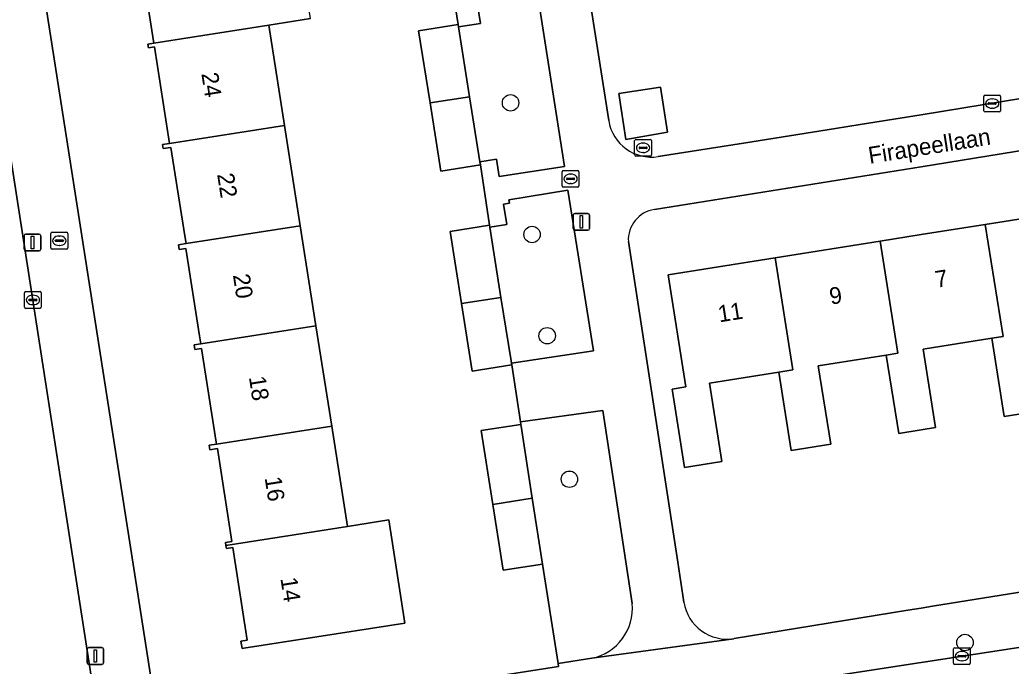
# Model space of a CAD drawing. Extents: x 160077 to 160948, y 386481 to 387498.
# Drawn here: x 160446.3 to 160505.4, y 387335.6 to 387374.1 of the extents above; entities that cross this region are included whole.
import ezdxf

# ---------------------------------------------------------------- set-up
doc = ezdxf.new("R2010")
doc.units = 0
for name, color, linetype in [('IMGEO_Boom', 7, 'Continuous'), ('IMGEO_Brandkraan', 7, 'Continuous'), ('IMGEO_Erf', 7, 'Continuous'), ('IMGEO_Groenvoorziening', 7, 'Continuous'), ('IMGEO_Kolk', 7, 'Continuous'), ('IMGEO_Lichtmast', 7, 'Continuous'), ('IMGEO_Openbare_ruimte_label', 7, 'Continuous'), ('IMGEO_Pand', 7, 'Continuous'), ('IMGEO_Pand_nummerreeks', 7, 'Continuous'), ('IMGEO_Rijbaan_lokaal_open', 7, 'Continuous'), ('IMGEO_Rioolput', 7, 'Continuous'), ('IMGEO_Voetpad_open', 7, 'Continuous')]:
    doc.layers.add(name, color=color, linetype=linetype)

msp = doc.modelspace()

# ---------------------------------------------------------------- linework, layer by layer
at = {"layer": 'IMGEO_Boom'}
for centre in [(160475.515, 387369.198), (160476.8, 387361.347), (160477.699, 387355.309), (160479.027, 387346.755), (160502.615, 387337.017)]:
    msp.add_circle(centre, 0.489, dxfattribs=at)
at = {"layer": 'IMGEO_Brandkraan'}
for p, q in [((160448.107, 387360.55), (160448.107, 387361.402)), ((160448.182, 387361.476), (160449.034, 387361.476)), ((160448.595, 387361.256), (160448.62, 387361.256)), ((160449.108, 387361.402), (160449.108, 387360.55)), ((160448.366, 387360.97), (160448.366, 387360.982)), ((160448.804, 387360.933), (160448.406, 387360.933)), ((160448.409, 387361.019), (160448.807, 387361.019)), ((160448.618, 387360.696), (160448.593, 387360.696)), ((160448.85, 387360.982), (160448.85, 387360.97)), ((160449.034, 387360.476), (160448.182, 387360.476))]:
    msp.add_line(p, q, dxfattribs=at)
for points in [[(160448.107, 387360.55), (160448.107, 387361.402)], [(160448.182, 387361.476), (160449.034, 387361.476)], [(160449.108, 387361.402), (160449.108, 387360.55)], [(160449.034, 387360.476), (160448.182, 387360.476)]]:
    msp.add_lwpolyline(points, dxfattribs=at)
for centre, radius, start, end in [((160448.184, 387361.4), 0.0765, 91.55205, 178.44795), ((160448.184, 387361.4), 0.0765, 91.55205, 178.44795), ((160449.032, 387361.4), 0.0765, 1.55205, 88.44795), ((160449.032, 387361.4), 0.0765, 1.55205, 88.44795), ((160448.406, 387360.979), 0.0403, 85.87752, 175.75265), ((160448.403, 387360.969), 0.0366, 178.93798, 274.71019), ((160448.807, 387360.976), 0.043, 264.86636, 352.45326), ((160448.811, 387360.981), 0.0386, 1.73085, 96.63898), ((160448.184, 387360.552), 0.0765, 181.55205, 268.44795), ((160448.184, 387360.552), 0.0765, 181.55205, 268.44795), ((160449.032, 387360.552), 0.0765, 271.55205, 358.44795), ((160449.032, 387360.552), 0.0765, 271.55205, 358.44795)]:
    msp.add_arc(centre, radius, start, end, dxfattribs=at)
for centre, major_axis, ratio, start_param, end_param in [((160448.594, 387360.976), (-0.387, 0.002), 0.722429, 4.712389, 7.853982), ((160448.619, 387360.976), (-0.39, 0.002), 0.717154, 1.570796, 4.712389)]:
    msp.add_ellipse(centre, major_axis=major_axis, ratio=ratio, start_param=start_param, end_param=end_param, dxfattribs=at)
at = {"layer": 'IMGEO_Erf'}
for points in [[(160468.816, 387381.159), (160468.202, 387385.029), (160470.554, 387385.403), (160469.911, 387389.457), (160467.557, 387389.085), (160466.918, 387393.126), (160466.238, 387397.42), (160468.592, 387397.792), (160468.029, 387401.353), (160465.675, 387400.981), (160465.025, 387405.092), (160464.34, 387409.42), (160466.693, 387409.792), (160466.137, 387413.304), (160463.783, 387412.932), (160463.13, 387417.058), (160462.455, 387421.323), (160464.809, 387421.695), (160464.247, 387425.247), (160440.528, 387421.423), (160454.195, 387334.054)], [(160478.041, 387389.373), (160481.371, 387368.134)], [(160456.866, 387332.235), (160478.373, 387335.585), (160478.346, 387335.761), (160477.421, 387341.696), (160475.067, 387341.33), (160474.455, 387345.254), (160473.769, 387349.66), (160476.123, 387350.026), (160476.101, 387350.173), (160475.583, 387353.575), (160473.23, 387353.201), (160472.591, 387357.225), (160471.91, 387361.519), (160474.263, 387361.893), (160473.715, 387365.492), (160471.363, 387365.118), (160470.715, 387369.195), (160470.033, 387373.491), (160472.386, 387373.865), (160471.813, 387377.477), (160469.46, 387377.103), (160468.816, 387381.159)], [(160463.577, 387374.218), (160461.106, 387373.831), (160462.041, 387367.854), (160462.977, 387361.866), (160463.913, 387355.9), (160464.849, 387349.922), (160465.785, 387343.945), (160468.252, 387344.331), (160469.214, 387338.181), (160468.307, 387338.039), (160459.618, 387336.678), (160459.507, 387336.661), (160459.438, 387337.103), (160459.814, 387337.162), (160458.949, 387342.685), (160458.568, 387342.625), (160458.539, 387342.811), (160458.514, 387342.973), (160458.9, 387343.034), (160458.031, 387348.585), (160457.576, 387348.514), (160457.535, 387348.777), (160457.97, 387348.845), (160457.952, 387348.959), (160457.077, 387354.547), (160456.692, 387354.487), (160456.648, 387354.763), (160457.049, 387354.826), (160456.973, 387355.311), (160456.158, 387360.515), (160455.753, 387360.452), (160455.708, 387360.739), (160456.163, 387360.81), (160456.091, 387361.271), (160455.265, 387366.54), (160454.802, 387366.468), (160454.765, 387366.704), (160455.186, 387366.77), (160454.284, 387372.531), (160453.919, 387372.474), (160453.883, 387372.7), (160454.236, 387372.763), (160453.345, 387378.454)], [(160484.327, 387365.994), (160489.406, 387366.799), (160494.896, 387367.669), (160496.357, 387367.901), (160500, 387368.49), (160507.39, 387369.685), (160508.893, 387369.93), (160514.628, 387370.867), (160520.489, 387371.785), (160521.678, 387371.943)], [(160522.075, 387368.967), (160520.672, 387368.738), (160500, 387365.375), (160484.096, 387362.839)], [(160507.096, 387350.827), (160504.961, 387350.487), (160504.219, 387355.157), (160500.12, 387354.505), (160500.862, 387349.835), (160500, 387349.698), (160498.667, 387349.486), (160497.925, 387354.156), (160493.867, 387353.511), (160494.61, 387348.841), (160492.256, 387348.467), (160491.513, 387353.136), (160487.377, 387352.478), (160488.12, 387347.808), (160485.895, 387347.454), (160485.152, 387352.124), (160485.974, 387352.255), (160484.911, 387358.939), (160491.287, 387359.953), (160497.557, 387360.95), (160500, 387361.339), (160503.828, 387361.948), (160510.098, 387362.945)], [(160482.54, 387360.92), (160485.484, 387341.815), (160485.854, 387339.415)], [(160488.852, 387337.254), (160499.213, 387338.948), (160500, 387339.075), (160500.683, 387339.185), (160505.767, 387339.991), (160519.324, 387342.142), (160523.935, 387342.867), (160526.171, 387343.197)]]:
    msp.add_lwpolyline(points, dxfattribs=at)
msp.add_lwpolyline([(160482.392, 387367.019), (160481.976, 387369.76), (160484.464, 387370.138), (160484.873, 387367.448)], close=True, dxfattribs=at)
for centre, radius, start, end in [((160483.922, 387368.547), 2.585, 189.18775, 279.00684), ((160484.374, 387361.023), 1.837, 98.70088, 183.22614), ((160488.429, 387339.828), 2.608, 189.10238, 279.32845)]:
    msp.add_arc(centre, radius, start, end, dxfattribs=at)
at = {"layer": 'IMGEO_Groenvoorziening'}
for points in [[(160477.106, 387375.835), (160473.51, 387375.257), (160473.524, 387375.163), (160473.719, 387373.933), (160472.408, 387373.725), (160473.069, 387369.563), (160473.685, 387365.68), (160474.673, 387365.836), (160474.837, 387364.8), (160478.735, 387365.403)], [(160478.936, 387363.988), (160475.413, 387363.407), (160475.443, 387363.21), (160475.097, 387363.155), (160475.289, 387361.944), (160474.28, 387361.784), (160474.945, 387357.594), (160475.544, 387353.822), (160475.569, 387353.666), (160480.463, 387354.419)]]:
    msp.add_lwpolyline(points, close=True, dxfattribs=at)
for points in [[(160481.012, 387350.858), (160476.101, 387350.173), (160476.123, 387350.026), (160476.141, 387349.913), (160476.809, 387345.623), (160477.421, 387341.696), (160478.346, 387335.761), (160480.358, 387336.079)], [(160482.768, 387339.346), (160481.012, 387350.858)]]:
    msp.add_lwpolyline(points, dxfattribs=at)
msp.add_arc((160479.739, 387339.058), 3.042, 281.73362, 5.43548, dxfattribs=at)
at = {"layer": 'IMGEO_Kolk'}
for p, q in [((160503.737, 387368.729), (160503.737, 387369.581)), ((160503.812, 387369.655), (160504.664, 387369.655)), ((160504.738, 387369.581), (160504.738, 387368.729)), ((160503.996, 387369.149), (160503.996, 387369.161)), ((160504.434, 387369.112), (160504.036, 387369.112)), ((160504.039, 387369.198), (160504.437, 387369.198)), ((160504.225, 387369.435), (160504.25, 387369.435)), ((160504.48, 387369.161), (160504.48, 387369.149)), ((160504.664, 387368.655), (160503.812, 387368.655)), ((160504.248, 387368.875), (160504.223, 387368.875)), ((160478.594, 387364.24), (160478.594, 387365.092)), ((160478.669, 387365.166), (160479.521, 387365.166)), ((160479.082, 387364.946), (160479.107, 387364.946)), ((160479.595, 387365.092), (160479.595, 387364.24)), ((160479.521, 387364.166), (160478.669, 387364.166)), ((160478.853, 387364.66), (160478.853, 387364.672)), ((160479.291, 387364.623), (160478.893, 387364.623)), ((160478.896, 387364.709), (160479.294, 387364.709)), ((160479.105, 387364.386), (160479.08, 387364.386)), ((160479.337, 387364.672), (160479.337, 387364.66)), ((160446.53, 387357.017), (160446.53, 387357.869)), ((160446.605, 387357.943), (160447.457, 387357.943)), ((160447.018, 387357.723), (160447.043, 387357.723)), ((160447.531, 387357.869), (160447.531, 387357.017)), ((160446.789, 387357.437), (160446.789, 387357.449)), ((160447.227, 387357.4), (160446.829, 387357.4)), ((160446.832, 387357.486), (160447.23, 387357.486)), ((160447.041, 387357.163), (160447.016, 387357.163)), ((160447.273, 387357.449), (160447.273, 387357.437)), ((160447.457, 387356.943), (160446.605, 387356.943)), ((160501.931, 387335.781), (160501.931, 387336.633)), ((160502.006, 387336.707), (160502.858, 387336.707)), ((160502.419, 387336.487), (160502.444, 387336.487)), ((160502.932, 387336.633), (160502.932, 387335.781)), ((160502.19, 387336.201), (160502.19, 387336.213)), ((160502.628, 387336.164), (160502.23, 387336.164)), ((160502.233, 387336.25), (160502.631, 387336.25)), ((160502.442, 387335.927), (160502.417, 387335.927)), ((160502.674, 387336.213), (160502.674, 387336.201)), ((160502.858, 387335.707), (160502.006, 387335.707))]:
    msp.add_line(p, q, dxfattribs=at)
for points in [[(160503.737, 387368.729), (160503.737, 387369.581)], [(160503.812, 387369.655), (160504.664, 387369.655)], [(160504.738, 387369.581), (160504.738, 387368.729)], [(160504.664, 387368.655), (160503.812, 387368.655)], [(160478.594, 387364.24), (160478.594, 387365.092)], [(160478.669, 387365.166), (160479.521, 387365.166)], [(160479.595, 387365.092), (160479.595, 387364.24)], [(160479.521, 387364.166), (160478.669, 387364.166)], [(160446.53, 387357.017), (160446.53, 387357.869)], [(160446.605, 387357.943), (160447.457, 387357.943)], [(160447.531, 387357.869), (160447.531, 387357.017)], [(160447.457, 387356.943), (160446.605, 387356.943)], [(160501.931, 387335.781), (160501.931, 387336.633)], [(160502.006, 387336.707), (160502.858, 387336.707)], [(160502.932, 387336.633), (160502.932, 387335.781)], [(160502.858, 387335.707), (160502.006, 387335.707)]]:
    msp.add_lwpolyline(points, dxfattribs=at)
for centre, radius, start, end in [((160503.814, 387369.579), 0.0765, 91.55205, 178.44795), ((160503.814, 387369.579), 0.0765, 91.55205, 178.44795), ((160504.662, 387369.579), 0.0765, 1.55205, 88.44795), ((160504.662, 387369.579), 0.0765, 1.55205, 88.44795), ((160504.036, 387369.158), 0.0403, 85.87752, 175.75265), ((160504.033, 387369.148), 0.0366, 178.93798, 274.71019), ((160504.437, 387369.155), 0.043, 264.86636, 352.45326), ((160504.441, 387369.16), 0.0386, 1.73085, 96.63898), ((160503.814, 387368.731), 0.0765, 181.55205, 268.44795), ((160503.814, 387368.731), 0.0765, 181.55205, 268.44795), ((160504.662, 387368.731), 0.0765, 271.55205, 358.44795), ((160504.662, 387368.731), 0.0765, 271.55205, 358.44795), ((160478.671, 387365.09), 0.0765, 91.55205, 178.44795), ((160478.671, 387365.09), 0.0765, 91.55205, 178.44795), ((160479.519, 387365.09), 0.0765, 1.55205, 88.44795), ((160479.519, 387365.09), 0.0765, 1.55205, 88.44795), ((160478.671, 387364.242), 0.0765, 181.55205, 268.44795), ((160478.671, 387364.242), 0.0765, 181.55205, 268.44795), ((160478.893, 387364.669), 0.0403, 85.87752, 175.75265), ((160478.89, 387364.659), 0.0366, 178.93798, 274.71019), ((160479.294, 387364.666), 0.043, 264.86636, 352.45326), ((160479.298, 387364.671), 0.0386, 1.73085, 96.63898), ((160479.519, 387364.242), 0.0765, 271.55205, 358.44795), ((160479.519, 387364.242), 0.0765, 271.55205, 358.44795), ((160446.607, 387357.867), 0.0765, 91.55205, 178.44795), ((160446.607, 387357.867), 0.0765, 91.55205, 178.44795), ((160447.455, 387357.867), 0.0765, 1.55205, 88.44795), ((160447.455, 387357.867), 0.0765, 1.55205, 88.44795), ((160446.829, 387357.446), 0.0403, 85.87752, 175.75265), ((160446.826, 387357.436), 0.0366, 178.93798, 274.71019), ((160447.23, 387357.443), 0.043, 264.86636, 352.45326), ((160447.234, 387357.448), 0.0386, 1.73085, 96.63898), ((160446.607, 387357.019), 0.0765, 181.55205, 268.44795), ((160446.607, 387357.019), 0.0765, 181.55205, 268.44795), ((160447.455, 387357.019), 0.0765, 271.55205, 358.44795), ((160447.455, 387357.019), 0.0765, 271.55205, 358.44795), ((160502.008, 387336.631), 0.0765, 91.55205, 178.44795), ((160502.008, 387336.631), 0.0765, 91.55205, 178.44795), ((160502.856, 387336.631), 0.0765, 1.55205, 88.44795), ((160502.856, 387336.631), 0.0765, 1.55205, 88.44795), ((160502.008, 387335.783), 0.0765, 181.55205, 268.44795), ((160502.008, 387335.783), 0.0765, 181.55205, 268.44795), ((160502.23, 387336.21), 0.0403, 85.87752, 175.75265), ((160502.227, 387336.2), 0.0366, 178.93798, 274.71019), ((160502.631, 387336.207), 0.043, 264.86636, 352.45326), ((160502.635, 387336.212), 0.0386, 1.73085, 96.63898), ((160502.856, 387335.783), 0.0765, 271.55205, 358.44795), ((160502.856, 387335.783), 0.0765, 271.55205, 358.44795)]:
    msp.add_arc(centre, radius, start, end, dxfattribs=at)
for centre, major_axis, ratio, start_param, end_param in [((160504.224, 387369.155), (-0.387, 0.002), 0.722429, 4.712389, 7.853982), ((160504.249, 387369.155), (-0.39, 0.002), 0.717154, 1.570796, 4.712389), ((160479.081, 387364.666), (-0.387, 0.002), 0.722429, 4.712389, 7.853982), ((160479.106, 387364.666), (-0.39, 0.002), 0.717154, 1.570796, 4.712389), ((160447.017, 387357.443), (-0.387, 0.002), 0.722429, 4.712389, 7.853982), ((160447.042, 387357.443), (-0.39, 0.002), 0.717154, 1.570796, 4.712389), ((160502.418, 387336.207), (-0.387, 0.002), 0.722429, 4.712389, 7.853982), ((160502.443, 387336.207), (-0.39, 0.002), 0.717154, 1.570796, 4.712389)]:
    msp.add_ellipse(centre, major_axis=major_axis, ratio=ratio, start_param=start_param, end_param=end_param, dxfattribs=at)
at = {"layer": 'IMGEO_Lichtmast'}
for p, q in [((160479.243, 387361.697), (160479.243, 387362.497)), ((160479.243, 387362.497), (160479.243, 387361.697)), ((160479.343, 387362.597), (160480.133, 387362.597)), ((160480.133, 387362.597), (160479.343, 387362.597)), ((160480.233, 387362.497), (160480.233, 387361.697)), ((160480.233, 387361.697), (160480.233, 387362.497)), ((160446.507, 387360.468), (160446.507, 387361.268)), ((160446.507, 387361.268), (160446.507, 387360.468)), ((160446.607, 387361.368), (160447.397, 387361.368)), ((160447.397, 387361.368), (160446.607, 387361.368)), ((160447.497, 387361.268), (160447.497, 387360.468)), ((160447.497, 387360.468), (160447.497, 387361.268)), ((160480.133, 387361.597), (160479.343, 387361.597)), ((160479.343, 387361.597), (160480.133, 387361.597)), ((160447.397, 387360.368), (160446.607, 387360.368)), ((160446.607, 387360.368), (160447.397, 387360.368)), ((160450.259, 387335.815), (160450.259, 387336.615)), ((160450.259, 387336.615), (160450.259, 387335.815)), ((160450.359, 387336.715), (160451.149, 387336.715)), ((160451.149, 387336.715), (160450.359, 387336.715)), ((160451.249, 387336.615), (160451.249, 387335.815)), ((160451.249, 387335.815), (160451.249, 387336.615)), ((160451.149, 387335.715), (160450.359, 387335.715)), ((160450.359, 387335.715), (160451.149, 387335.715))]:
    msp.add_line(p, q, dxfattribs=at)
for points in [[(160479.663, 387362.472), (160479.813, 387362.472), (160479.813, 387361.722), (160479.663, 387361.722), (160479.663, 387362.472)], [(160446.927, 387361.243), (160447.077, 387361.243), (160447.077, 387360.493), (160446.927, 387360.493), (160446.927, 387361.243)], [(160450.679, 387336.59), (160450.829, 387336.59), (160450.829, 387335.84), (160450.679, 387335.84), (160450.679, 387336.59)]]:
    msp.add_lwpolyline(points, dxfattribs=at)
for centre, start, end in [((160479.343, 387362.497), 90, 180), ((160479.343, 387362.497), 90, 180), ((160480.133, 387362.497), 0, 90), ((160480.133, 387362.497), 360, 90), ((160446.607, 387361.268), 90, 180), ((160446.607, 387361.268), 90, 180), ((160447.397, 387361.268), 0, 90), ((160447.397, 387361.268), 360, 90), ((160479.343, 387361.697), 180, 270), ((160479.343, 387361.697), 180, 270), ((160480.133, 387361.697), 270, 0), ((160480.133, 387361.697), 270, 0), ((160446.607, 387360.468), 180, 270), ((160446.607, 387360.468), 180, 270), ((160447.397, 387360.468), 270, 0), ((160447.397, 387360.468), 270, 0), ((160450.359, 387336.615), 90, 180), ((160450.359, 387336.615), 90, 180), ((160451.149, 387336.615), 0, 90), ((160451.149, 387336.615), 360, 90), ((160450.359, 387335.815), 180, 270), ((160450.359, 387335.815), 180, 270), ((160451.149, 387335.815), 270, 0), ((160451.149, 387335.815), 270, 0)]:
    msp.add_arc(centre, 0.1, start, end, dxfattribs=at)
at = {"layer": 'IMGEO_Pand'}
for points in [[(160462.642, 387380.196), (160460.17, 387379.809), (160453.29, 387378.731), (160452.911, 387378.672), (160452.954, 387378.393), (160453.345, 387378.454), (160454.236, 387372.763), (160461.106, 387373.831), (160463.577, 387374.218)], [(160461.106, 387373.831), (160454.236, 387372.763), (160453.883, 387372.7), (160453.919, 387372.474), (160454.284, 387372.531), (160455.186, 387366.77), (160462.041, 387367.854)], [(160472.408, 387373.725), (160472.386, 387373.865), (160470.033, 387373.491), (160470.715, 387369.195), (160473.069, 387369.563)], [(160482.392, 387367.019), (160484.873, 387367.448), (160484.464, 387370.138), (160481.976, 387369.76)], [(160473.069, 387369.563), (160470.715, 387369.195), (160471.363, 387365.118), (160473.715, 387365.492), (160473.685, 387365.68)], [(160462.041, 387367.854), (160455.186, 387366.77), (160454.765, 387366.704), (160454.802, 387366.468), (160455.265, 387366.54), (160456.091, 387361.271), (160456.163, 387360.81), (160462.977, 387361.866)], [(160504.219, 387355.157), (160504.961, 387350.487), (160507.096, 387350.827), (160506.354, 387355.496), (160510.59, 387356.17), (160511.16, 387356.261), (160510.098, 387362.945), (160503.828, 387361.948), (160504.891, 387355.261)], [(160462.977, 387361.866), (160456.163, 387360.81), (160455.708, 387360.739), (160455.753, 387360.452), (160456.158, 387360.515), (160456.973, 387355.311), (160457.049, 387354.826), (160463.913, 387355.9)], [(160474.28, 387361.784), (160474.263, 387361.893), (160471.91, 387361.519), (160472.591, 387357.225), (160474.945, 387357.594)], [(160504.891, 387355.261), (160503.828, 387361.948), (160500, 387361.339), (160497.557, 387360.95), (160498.62, 387354.265), (160497.925, 387354.156), (160498.667, 387349.486), (160500, 387349.698), (160500.862, 387349.835), (160500.12, 387354.505), (160504.219, 387355.157)], [(160498.62, 387354.265), (160497.557, 387360.95), (160491.287, 387359.953), (160492.35, 387353.267), (160491.513, 387353.136), (160492.256, 387348.467), (160494.61, 387348.841), (160493.867, 387353.511), (160497.925, 387354.156)], [(160492.35, 387353.267), (160491.287, 387359.953), (160484.911, 387358.939), (160485.974, 387352.255), (160485.152, 387352.124), (160485.895, 387347.454), (160488.12, 387347.808), (160487.377, 387352.478), (160491.513, 387353.136)], [(160474.945, 387357.594), (160472.591, 387357.225), (160473.23, 387353.201), (160475.583, 387353.575), (160475.569, 387353.666), (160475.544, 387353.822)], [(160463.913, 387355.9), (160457.049, 387354.826), (160456.648, 387354.763), (160456.692, 387354.487), (160457.077, 387354.547), (160457.952, 387348.959), (160457.97, 387348.845), (160464.849, 387349.922)], [(160476.141, 387349.913), (160476.123, 387350.026), (160473.769, 387349.66), (160474.455, 387345.254), (160476.809, 387345.623)], [(160464.849, 387349.922), (160457.97, 387348.845), (160457.535, 387348.777), (160457.576, 387348.514), (160458.031, 387348.585), (160458.9, 387343.034), (160458.514, 387342.973), (160458.539, 387342.811), (160465.785, 387343.945)], [(160476.809, 387345.623), (160474.455, 387345.254), (160475.067, 387341.33), (160477.421, 387341.696)], [(160468.252, 387344.331), (160465.785, 387343.945), (160458.539, 387342.811), (160458.568, 387342.625), (160458.949, 387342.685), (160459.814, 387337.162), (160459.438, 387337.103), (160459.507, 387336.661), (160459.618, 387336.678), (160468.307, 387338.039), (160469.214, 387338.181)]]:
    msp.add_lwpolyline(points, close=True, dxfattribs=at)
at = {"layer": 'IMGEO_Rijbaan_lokaal_open'}
for points in [[(160456.945, 387294.39), (160456.089, 387299.755), (160453.651, 387315.452), (160453.642, 387315.457), (160450.699, 387333.585), (160450.725, 387333.607), (160445.185, 387369.339)], [(160529.129, 387340.636), (160528.643, 387340.566), (160526.431, 387340.245), (160523.231, 387339.751), (160506.86, 387336.889), (160500, 387335.831), (160480.714, 387332.858), (160477.592, 387332.362), (160473.856, 387331.768), (160456.939, 387329.08)]]:
    msp.add_lwpolyline(points, dxfattribs=at)
at = {"layer": 'IMGEO_Rioolput'}
for p, q in [((160482.917, 387366.09), (160482.917, 387366.942)), ((160482.992, 387367.016), (160483.844, 387367.016)), ((160483.219, 387366.559), (160483.617, 387366.559)), ((160483.405, 387366.796), (160483.43, 387366.796)), ((160483.918, 387366.942), (160483.918, 387366.09)), ((160483.844, 387366.016), (160482.992, 387366.016)), ((160483.176, 387366.51), (160483.176, 387366.522)), ((160483.614, 387366.473), (160483.216, 387366.473)), ((160483.428, 387366.236), (160483.403, 387366.236)), ((160483.66, 387366.522), (160483.66, 387366.51))]:
    msp.add_line(p, q, dxfattribs=at)
for points in [[(160482.917, 387366.09), (160482.917, 387366.942)], [(160482.992, 387367.016), (160483.844, 387367.016)], [(160483.918, 387366.942), (160483.918, 387366.09)], [(160483.844, 387366.016), (160482.992, 387366.016)]]:
    msp.add_lwpolyline(points, dxfattribs=at)
for centre, radius, start, end in [((160482.994, 387366.94), 0.0765, 91.55205, 178.44795), ((160482.994, 387366.94), 0.0765, 91.55205, 178.44795), ((160483.216, 387366.519), 0.0403, 85.87752, 175.75265), ((160483.621, 387366.521), 0.0386, 1.73085, 96.63898), ((160483.842, 387366.94), 0.0765, 1.55205, 88.44795), ((160483.842, 387366.94), 0.0765, 1.55205, 88.44795), ((160482.994, 387366.092), 0.0765, 181.55205, 268.44795), ((160482.994, 387366.092), 0.0765, 181.55205, 268.44795), ((160483.213, 387366.509), 0.0366, 178.93798, 274.71019), ((160483.617, 387366.516), 0.043, 264.86636, 352.45326), ((160483.842, 387366.092), 0.0765, 271.55205, 358.44795), ((160483.842, 387366.092), 0.0765, 271.55205, 358.44795)]:
    msp.add_arc(centre, radius, start, end, dxfattribs=at)
for centre, major_axis, ratio, start_param, end_param in [((160483.404, 387366.516), (-0.387, 0.002), 0.722429, 4.712389, 7.853982), ((160483.429, 387366.516), (-0.39, 0.002), 0.717154, 1.570796, 4.712389)]:
    msp.add_ellipse(centre, major_axis=major_axis, ratio=ratio, start_param=start_param, end_param=end_param, dxfattribs=at)
at = {"layer": 'IMGEO_Voetpad_open'}
for points in [[(160433.965, 387439.947), (160439.731, 387403.919), (160445.185, 387369.339), (160450.725, 387333.607)], [(160454.961, 387329.131), (160454.195, 387334.054), (160440.528, 387421.423), (160440.28, 387423.011), (160437.638, 387439.901)], [(160481.371, 387368.134), (160478.041, 387389.373)], [(160471.813, 387377.477), (160472.386, 387373.865), (160472.408, 387373.725), (160473.719, 387373.933), (160473.524, 387375.163)], [(160477.106, 387375.835), (160478.735, 387365.403), (160474.837, 387364.8), (160474.673, 387365.836), (160473.685, 387365.68), (160473.715, 387365.492), (160474.263, 387361.893), (160474.28, 387361.784), (160475.289, 387361.944), (160475.097, 387363.155), (160475.443, 387363.21), (160475.413, 387363.407), (160478.936, 387363.988), (160480.463, 387354.419), (160475.569, 387353.666), (160475.583, 387353.575), (160476.101, 387350.173), (160481.012, 387350.858), (160482.768, 387339.346)], [(160521.678, 387371.943), (160520.489, 387371.785), (160514.628, 387370.867), (160508.893, 387369.93), (160507.39, 387369.685), (160500, 387368.49), (160496.357, 387367.901), (160494.896, 387367.669), (160489.406, 387366.799), (160484.327, 387365.994)], [(160484.096, 387362.839), (160500, 387365.375), (160520.672, 387368.738), (160522.075, 387368.967)], [(160485.854, 387339.415), (160485.484, 387341.815), (160482.54, 387360.92)], [(160526.171, 387343.197), (160523.935, 387342.867), (160519.324, 387342.142), (160505.767, 387339.991), (160500.683, 387339.185), (160500, 387339.075), (160499.213, 387338.948), (160488.852, 387337.254), (160488.83, 387337.236), (160480.358, 387336.079), (160478.346, 387335.761), (160478.373, 387335.585), (160456.866, 387332.235)], [(160456.939, 387329.08), (160473.856, 387331.768), (160473.779, 387332.261), (160477.515, 387332.855), (160477.592, 387332.362), (160480.714, 387332.858), (160500, 387335.831), (160506.86, 387336.889), (160523.231, 387339.751)], [(160480.358, 387336.079), (160488.83, 387337.236), (160488.852, 387337.254)]]:
    msp.add_lwpolyline(points, dxfattribs=at)
for centre, radius, start, end in [((160483.922, 387368.547), 2.585, 189.18775, 279.00684), ((160484.374, 387361.023), 1.837, 98.70088, 183.22614), ((160479.739, 387339.058), 3.042, 281.73362, 5.43548), ((160488.429, 387339.828), 2.608, 189.10238, 279.32845)]:
    msp.add_arc(centre, radius, start, end, dxfattribs=at)

# ---------------------------------------------------------------- texts
at = {"layer": 'IMGEO_Openbare_ruimte_label'}
msp.add_text('Firapeellaan', height=1, rotation=9.0292, dxfattribs=at).set_placement((160496.932, 387365.561))
at = {"layer": 'IMGEO_Pand_nummerreeks'}
for s, rotation, p in [('24', 278.90355, (160457.074, 387370.937)), ('22', 278.90355, (160458.014, 387364.938)), ('20', 278.90355, (160458.955, 387358.93)), ('7', 9.03599, (160500.918, 387358.163)), ('9', 9.03599, (160494.612, 387357.16)), ('11', 9.03599, (160487.965, 387356.104)), ('18', 278.90355, (160459.909, 387352.838)), ('16', 278.90355, (160460.849, 387346.839)), ('14', 278.90355, (160461.789, 387340.838))]:
    msp.add_text(s, height=1, rotation=rotation, dxfattribs=at).set_placement(p)

doc.saveas('drawing.dxf')
